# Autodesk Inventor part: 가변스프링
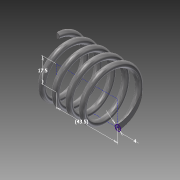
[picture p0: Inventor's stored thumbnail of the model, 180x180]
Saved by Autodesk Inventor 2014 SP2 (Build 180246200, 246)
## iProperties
Created: 2015-03
Part Number: 가변스프링
Material: 강철, 탄소
Document SubType Name: Modeling
Designer: 201-01
Density: 7.87 g/cm^3
Appearance: 반연마
Mass: 47.9808 g
Surface Area: 62.0298 cm^2
Volume: 6.09668 cm^3
Author: 201-01
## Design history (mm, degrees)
sketch "스케치2"
  geometry: L1 (0, 0)-(43.5, 0); L2 (43.5, 0)-(43.5, -17.5); L3 (43.5, -17.5)-(0, -17.5); L4 (0, -17.5)-(0, 0); C1 r 2 at (0, -17.5)
  constraints: 8 end point, 2 parallel, 1 centre point, 1 coincident, 1 horizontal, 1 perpendicular
  dimensions: "d0" = 17.5 distance of L1.end L2.end; "d1" = 43.5 distance of L2.end L3.end (derived); "d2" = 4 diameter of C1
feature "코일1" sketch "스케치2" pitch "d3" = 10; turns "d5" = 4.5; dims "d4" = 43.5 (= d1), "d6" = 0, angle "d7" = 90 deg, angle "d8" = 90 deg, "d9" = 0, "d10" = 0
sketch "스케치3"
  geometry: L1 (0, -19.5)-(0, -15.5) reference; 1 further point
  constraints: 1 vertical alignment
extrude "돌출1" cut sketch "스케치3" distance "d11" = 10; taper "d12" = 0 deg
node "작업 평면1"
sketch "스케치4"
  geometry: L1 (0, 15.5)-(0, 19.5) reference; 2 further points
  constraints: 2 other
extrude "돌출2" cut sketch "스케치4" distance "d13" = 10; taper "d14" = 0 deg
node "솔리드1"
node "절단 모서리 투영1"
node "절단 모서리 투영2"
